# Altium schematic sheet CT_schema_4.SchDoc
size 524 x 490 mm
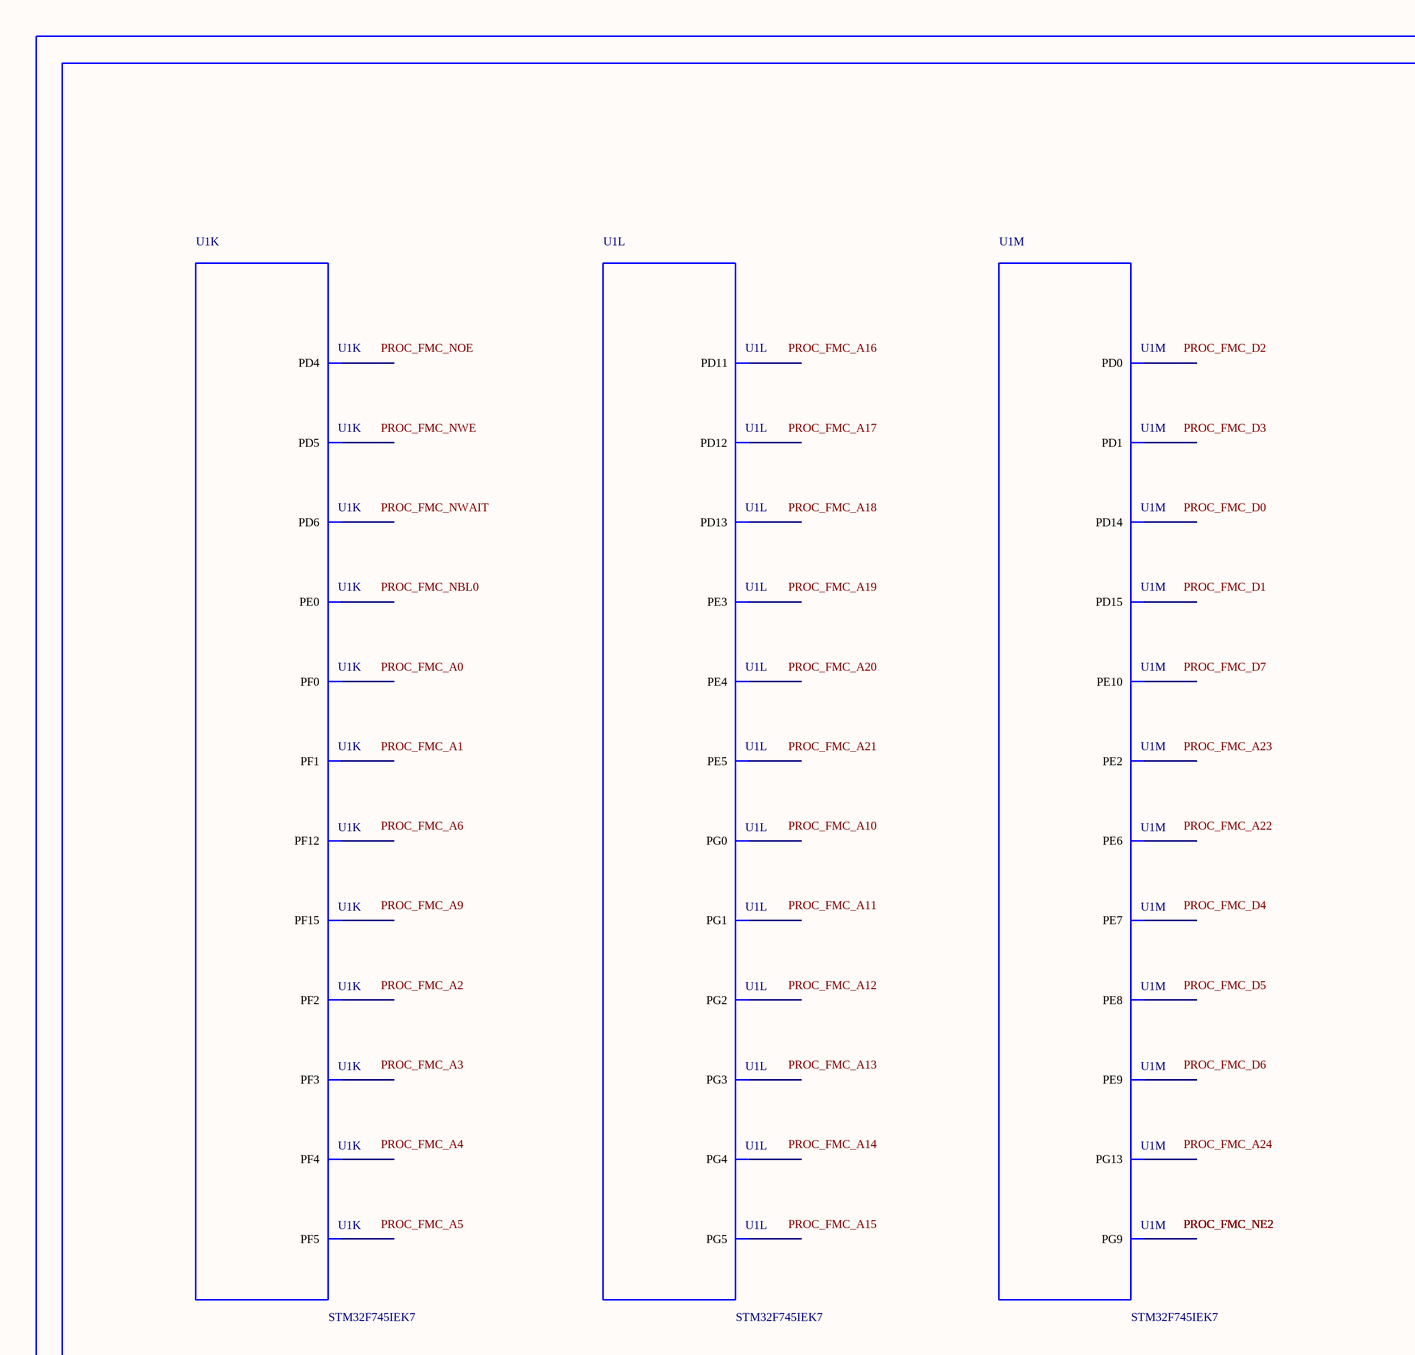
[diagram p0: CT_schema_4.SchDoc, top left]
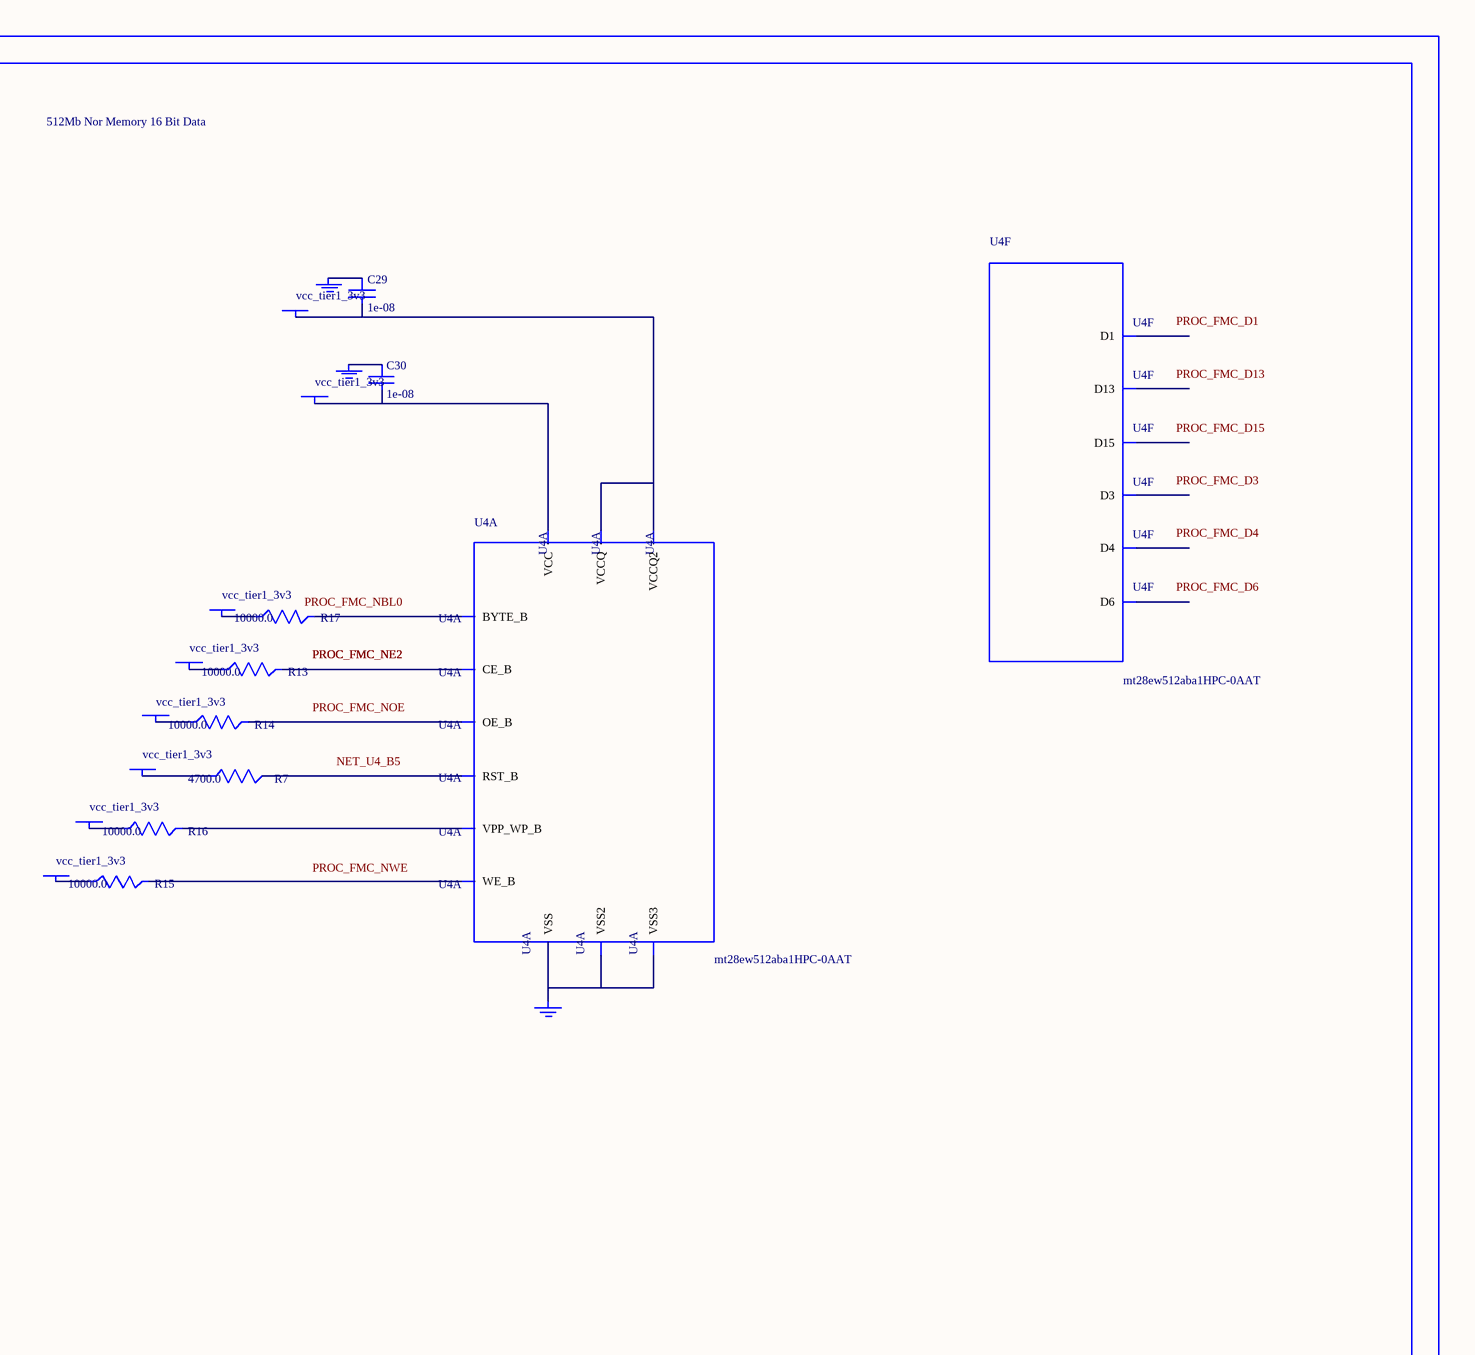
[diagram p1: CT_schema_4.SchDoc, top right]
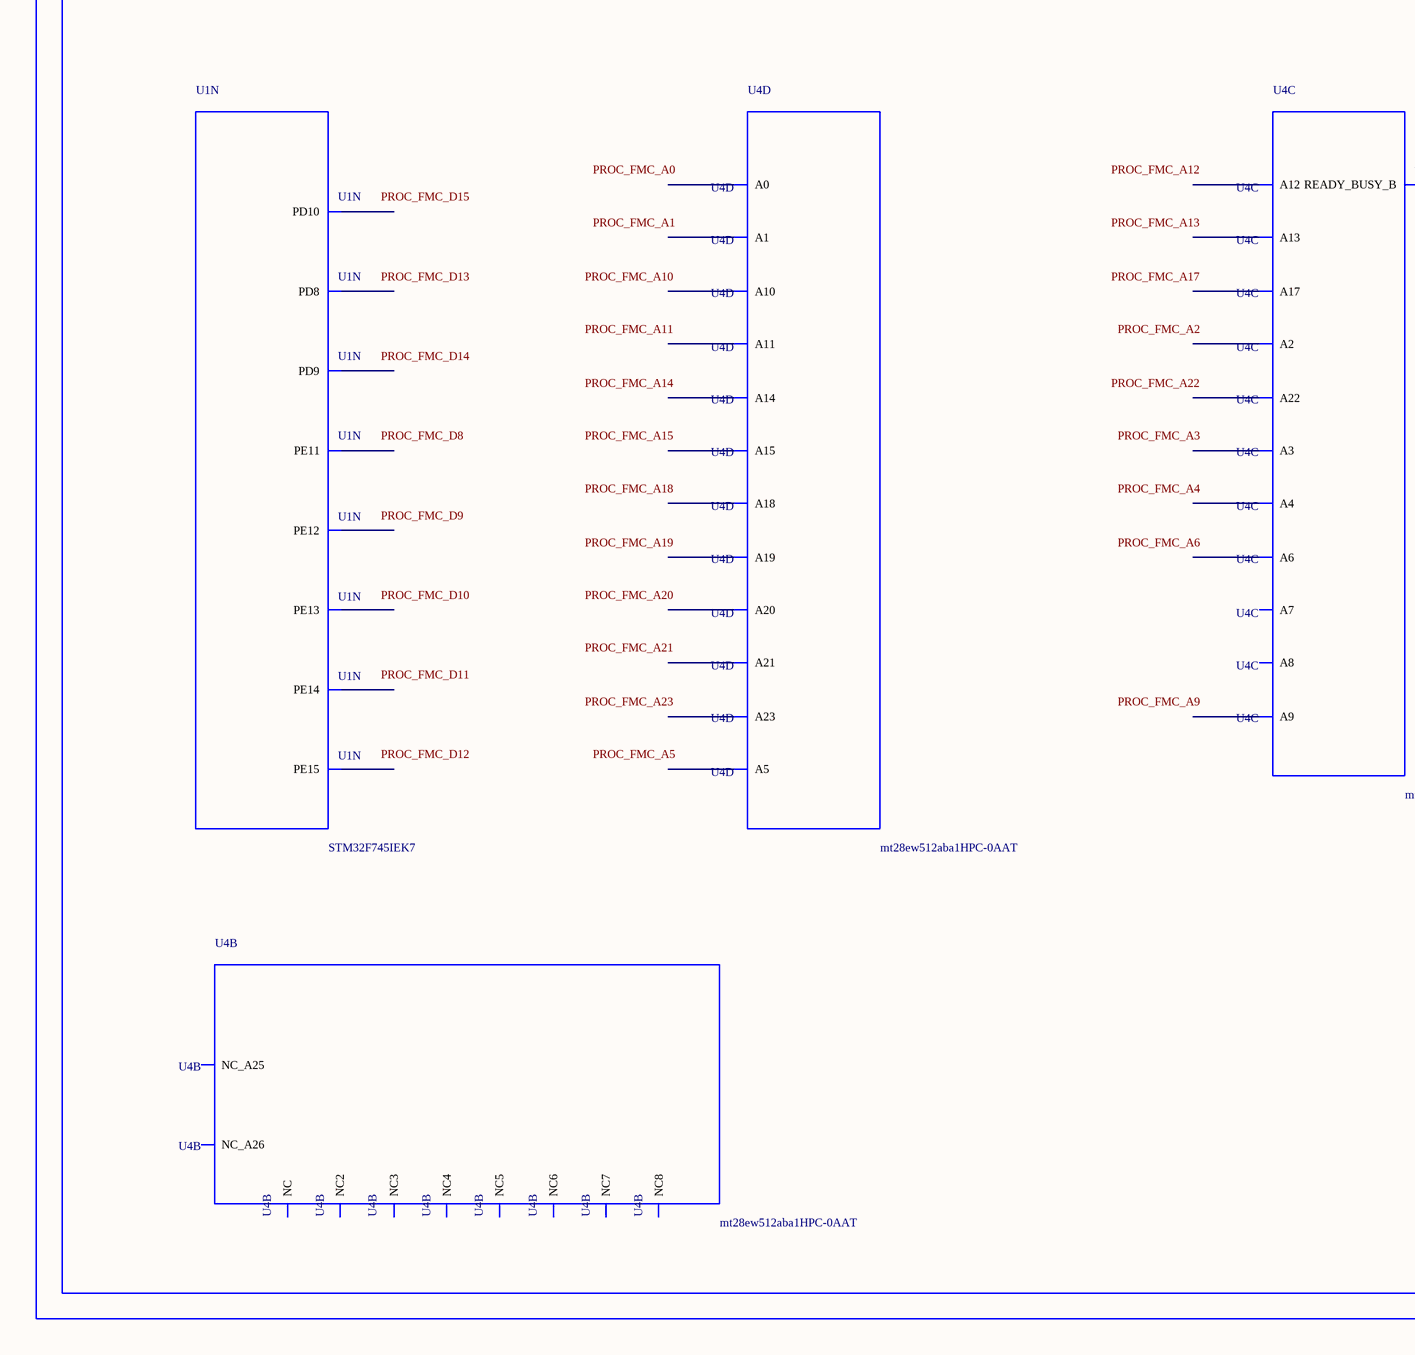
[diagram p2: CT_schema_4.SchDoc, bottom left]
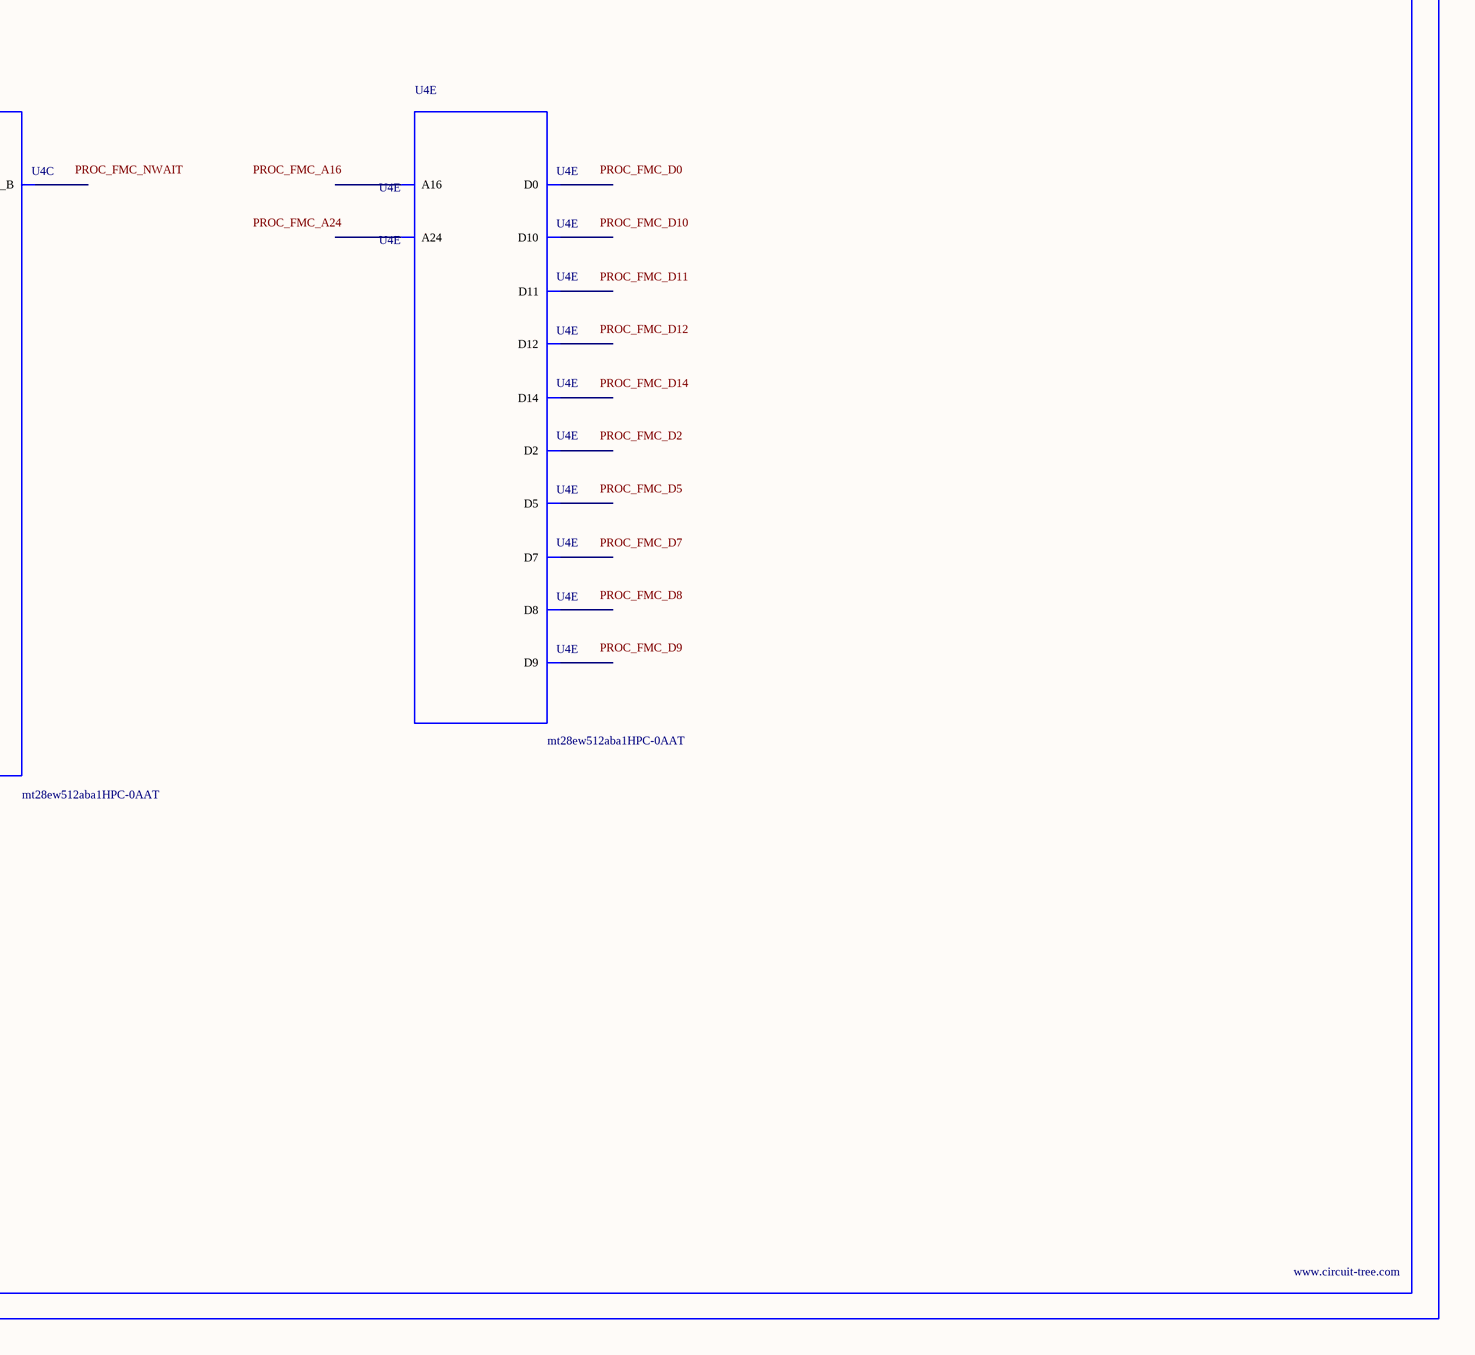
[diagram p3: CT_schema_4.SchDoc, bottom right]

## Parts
BORDER3  (no value)
C29  1e-08  [C0402]
C30  1e-08  [C0402]
GND_INSTANCE_3_0  (no value)
GND_INSTANCE_3_1  (no value)
GND_INSTANCE_3_2  (no value)
POWER_INSTANCE_3_0  vcc_tier1_3v3
POWER_INSTANCE_3_1  vcc_tier1_3v3
POWER_INSTANCE_3_2  vcc_tier1_3v3
POWER_INSTANCE_3_3  vcc_tier1_3v3
POWER_INSTANCE_3_4  vcc_tier1_3v3
POWER_INSTANCE_3_5  vcc_tier1_3v3
POWER_INSTANCE_3_6  vcc_tier1_3v3
POWER_INSTANCE_3_7  vcc_tier1_3v3
R7  4700.0  [R0603]
R13  10000.0  [R0603]
R14  10000.0  [R0603]
R15  10000.0  [R0603]
R16  10000.0  [R0603]
R17  10000.0  [R0603]
U1  STM32F745IEK7  [UFBGA176_25]  (parts K,L,M,N of 14)
U4  mt28ew512aba1HPC-0AAT  [LBGA-64]  (parts A,B,C,D,E,F of 6)

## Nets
NetC29_1: C29.1 GND_INSTANCE_3_0.0(GND)
NetC29_2: C29.2 POWER_INSTANCE_3_0.0(PWR) U4.D8(VCCQ) U4.F1(VCCQ2)
NetC30_1: C30.1 GND_INSTANCE_3_1.0(GND)
NetC30_2: C30.2 POWER_INSTANCE_3_1.0(PWR) U4.G5(VCC)
NetGND_INSTANCE_3_2_0: GND_INSTANCE_3_2.0(GND) U4.E8(VSS) U4.H2(VSS2) U4.H7(VSS3)
NetPOWER_INSTANCE_3_2_0: POWER_INSTANCE_3_2.0(PWR) R13.1
NetPOWER_INSTANCE_3_3_0: POWER_INSTANCE_3_3.0(PWR) R14.1
NetPOWER_INSTANCE_3_4_0: POWER_INSTANCE_3_4.0(PWR) R15.1
NetPOWER_INSTANCE_3_5_0: POWER_INSTANCE_3_5.0(PWR) R16.1
NetPOWER_INSTANCE_3_6_0: POWER_INSTANCE_3_6.0(PWR) R17.1
NetPOWER_INSTANCE_3_7_0: POWER_INSTANCE_3_7.0(PWR) R7.1
NetR7_2: R7.2 U4.B5(RST_B)
NetR13_2: R13.2 U4.F2(CE_B)
NetR14_2: R14.2 U4.G2(OE_B)
NetR15_2: R15.2 U4.A5(WE_B)
NetR16_2: R16.2 U4.B4(VPP_WP_B)
NetR17_2: R17.2 U4.F7(BYTE_B)

Not connected (* = marked no-connect by the designer): U1 A1(PE3) A2(PE2) A4(PE0) A8(PG13) B1(PE4) B2(PE5) B3(PE6) B11(PD6) B12(PD0) C10(PG9) C11(PD5) C12(PD1) D10(PD4) E2(PF0) H2(PF2) H3(PF1) J2(PF3) J3(PF4) K3(PF5) K13(PG5) K14(PG4) K15(PG3) L14(PD15) L15(PG2) M7(PG1) M14(PD14) M15(PD13) N7(PG0) N11(PE13) N13(PD12) N14(PD11) N15(PD10) P6(PF12) P7(PF15) P8(PE8) P9(PE9) P10(PE11) P11(PE14) P14(PD9) P15(PD8) R8(PE7) R9(PE10) R10(PE12) R11(PE15); U4 A1(NC) A2(A3) A3(A7) A4(READY_BUSY_B) A6(A9) A7(A13) A8(NC2) B1(NC_A26) B2(A4) B3(A17) B6(A8) B7(A12) B8(A22) C1(NC3) C2(A2) C3(A6) C4(A18) C5(A21) C6(A10) C7(A14) C8(A23) D1(NC4) D2(A1) D3(A5) D4(A20) D5(A19) D6(A11) D7(A15) E1(NC5) E2(A0) E3(D0) E4(D2) E5(D5) E6(D7) E7(A16) F3(D8) F4(D10) F5(D12) F6(D14) F8(A24) G1(NC6) G3(D9) G4(D11) G6(D13) G7(D15) G8(NC_A25) H1(NC7) H3(D1) H4(D3) H5(D4) H6(D6) H8(NC8)

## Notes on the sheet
- Labels drawn without touching a wire or pin: NET_U4_B5, PROC_FMC_A0, PROC_FMC_A1, PROC_FMC_A2, PROC_FMC_A3, PROC_FMC_A4, PROC_FMC_A5, PROC_FMC_A6, PROC_FMC_A9, PROC_FMC_A10, PROC_FMC_A11, PROC_FMC_A12, PROC_FMC_A13, PROC_FMC_A14, PROC_FMC_A15, PROC_FMC_A16, PROC_FMC_A17, PROC_FMC_A18, PROC_FMC_A19, PROC_FMC_A20, PROC_FMC_A21, PROC_FMC_A22, PROC_FMC_A23, PROC_FMC_A24, PROC_FMC_D0, PROC_FMC_D1, PROC_FMC_D2, PROC_FMC_D3, PROC_FMC_D4, PROC_FMC_D5, PROC_FMC_D6, PROC_FMC_D7, PROC_FMC_D8, PROC_FMC_D9, PROC_FMC_D10, PROC_FMC_D11, PROC_FMC_D12, PROC_FMC_D13, PROC_FMC_D14, PROC_FMC_D15, PROC_FMC_NBL0, PROC_FMC_NOE, PROC_FMC_NWAIT, PROC_FMC_NWE

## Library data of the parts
BORDER3 = BORDER_PAGE3
C29 C30 = C0402C103K3RAC
GND_INSTANCE_3_0-GND_INSTANCE_3_2 = GND
POWER_INSTANCE_3_0-POWER_INSTANCE_3_7 = PWR
R7 = RC0603JR-074K7L
R13-R17 = RC0603JR-0710KL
